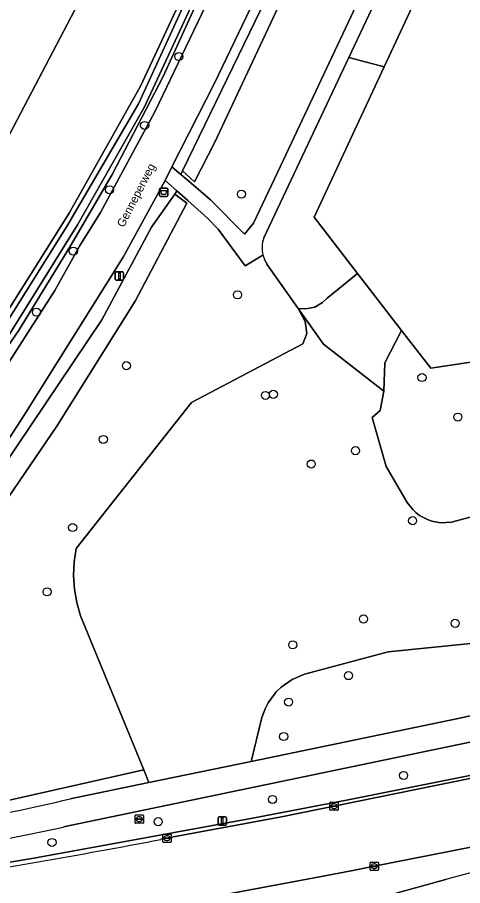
# Model space of a CAD drawing. Extents: x 160203 to 161530, y 379528 to 381797.
# Drawn here: x 160867 to 160920.7, y 380873.7 to 380978.3 of the extents above; entities that cross this region are included whole.
import ezdxf

# ---------------------------------------------------------------- set-up
doc = ezdxf.new("R2010")
doc.units = 0
for name, color, linetype in [('IMGEO_Afvalbak', 7, 'Continuous'), ('IMGEO_Berm_groen', 7, 'Continuous'), ('IMGEO_Boom', 7, 'Continuous'), ('IMGEO_Erf', 7, 'Continuous'), ('IMGEO_Fietspad_gesloten', 7, 'Continuous'), ('IMGEO_Grasland_agrarisch', 7, 'Continuous'), ('IMGEO_Groenvoorziening', 7, 'Continuous'), ('IMGEO_Kolk', 7, 'Continuous'), ('IMGEO_Lichtmast', 7, 'Continuous'), ('IMGEO_Loofbos', 7, 'Continuous'), ('IMGEO_Oever', 7, 'Continuous'), ('IMGEO_Openbare_ruimte_label', 7, 'Continuous'), ('IMGEO_Rijbaan_lokaal_gesloten', 7, 'Continuous'), ('IMGEO_Rijbaan_lokaal_open', 7, 'Continuous'), ('IMGEO_Rioolput', 7, 'Continuous'), ('IMGEO_Terreindeel_halfverhard', 7, 'Continuous'), ('IMGEO_Voetpad_halfverhard', 7, 'Continuous'), ('IMGEO_Voetpad_open', 7, 'Continuous'), ('IMGEO_Waterloop', 7, 'Continuous')]:
    doc.layers.add(name, color=color, linetype=linetype)

msp = doc.modelspace()

# ---------------------------------------------------------------- linework, layer by layer
at = {"layer": 'IMGEO_Afvalbak'}
for p, q in [((160884.18, 380956.88), (160884.18, 380957.67)), ((160884.18, 380957.67), (160884.18, 380956.88)), ((160884.28, 380957.77), (160885.07, 380957.77)), ((160885.07, 380957.77), (160884.28, 380957.77)), ((160885.17, 380957.67), (160885.17, 380956.88)), ((160885.17, 380956.88), (160885.17, 380957.67)), ((160885.07, 380956.78), (160884.28, 380956.78)), ((160884.28, 380956.78), (160885.07, 380956.78))]:
    msp.add_line(p, q, dxfattribs=at)
msp.add_lwpolyline([(160884.32, 380957.49), (160885.03, 380957.49), (160884.88, 380957.02), (160884.47, 380957.02), (160884.32, 380957.49)], dxfattribs=at)
for centre, start, end in [((160884.28, 380957.67), 90, 180), ((160884.28, 380957.67), 90, 180), ((160885.07, 380957.67), 0, 90), ((160885.07, 380957.67), 360, 90), ((160884.28, 380956.88), 180, 270), ((160884.28, 380956.88), 180, 270), ((160885.07, 380956.88), 270, 0), ((160885.07, 380956.88), 270, 0)]:
    msp.add_arc(centre, 0.1, start, end, dxfattribs=at)
at = {"layer": 'IMGEO_Berm_groen'}
msp.add_lwpolyline([(160903.11, 380993.15), (160903.75, 380994.27), (160903.74, 380994.85), (160902.43, 380994.82), (160901.43, 380992.62), (160890.8, 380970.43), (160885.68, 380960.32), (160886.73, 380959.43), (160886.96, 380959.86)], close=True, dxfattribs=at)
for points in [[(160934.56, 380893.86), (160921, 380890.93), (160872.61, 380880.82)], [(160998.03, 380891.65), (160999.49, 380891.83), (160989.42, 380892.42), (160952.06, 380884.24), (160949.3, 380883.67), (160949.22, 380884.02), (160939.29, 380881.99), (160930.13, 380880.09), (160925.35, 380879.1), (160916.8, 380877.42), (160910.05, 380876.08), (160907.28, 380875.55), (160901.96, 380874.53), (160894.01, 380873.03), (160886.98, 380871.73), (160886.33, 380871.62), (160884.79, 380871.34), (160882.6, 380870.58), (160869.67, 380866.12), (160869.92, 380864.47), (160867.84, 380864.13), (160868.11, 380862.53), (160872.74, 380863.26)], [(160850.52, 380876.66), (160860.78, 380875.68), (160869.03, 380877.04), (160882.43, 380879.51), (160895.18, 380881.82), (160906.72, 380884.04), (160922.19, 380887.13), (160938.38, 380890.52)], [(160893.97, 380867.8), (160903.4, 380870.29), (160918.79, 380874.53)]]:
    msp.add_lwpolyline(points, dxfattribs=at)
for centre, radius, start, end in [((160785.98, 381281.03), 409.49, 279.0693, 282.2148), ((161014.42, 380515.59), 371.47, 101.8451, 104.9191)]:
    msp.add_arc(centre, radius, start, end, dxfattribs=at)
at = {"layer": 'IMGEO_Boom'}
for centre in [(160886.5, 380973.62), (160882.39, 380965.32), (160878.15, 380957.57), (160894.05, 380957.04), (160873.79, 380950.18), (160893.57, 380944.92), (160869.35, 380942.83), (160880.19, 380936.39), (160915.81, 380934.95), (160896.94, 380932.8), (160897.9, 380932.93), (160920.12, 380930.19), (160877.41, 380927.5), (160907.79, 380926.14), (160902.46, 380924.53), (160873.71, 380916.88), (160914.67, 380917.71), (160870.63, 380909.14), (160908.76, 380905.87), (160919.81, 380905.35), (160900.23, 380902.76), (160906.94, 380899.05), (160899.73, 380895.86), (160899.14, 380891.71), (160913.58, 380887.02), (160897.79, 380884.13), (160884.02, 380881.46), (160871.22, 380878.95)]:
    msp.add_circle(centre, 0.489, dxfattribs=at)
at = {"layer": 'IMGEO_Erf'}
msp.add_lwpolyline([(160917.68, 380986.21), (160911.25, 380972.39), (160902.81, 380954.26), (160908.04, 380947.49), (160913.35, 380940.61), (160916.86, 380936.07), (160938.04, 380939.26), (160974.07, 380944.7), (160994.32, 380947.75), (160994.25, 380948.88), (160993.58, 380960.43), (160993.57, 380960.53), (160993.21, 380965.37), (160992.81, 380974.25), (160992.03, 380991.59)], dxfattribs=at)
at = {"layer": 'IMGEO_Fietspad_gesloten'}
for points in [[(160933.75, 380896.85), (160929.16, 380895.85), (160920.18, 380893.89), (160895.22, 380888.71), (160882.91, 380886.16), (160873.42, 380884.2)], [(160872.61, 380880.82), (160921, 380890.93), (160934.56, 380893.86)]]:
    msp.add_lwpolyline(points, dxfattribs=at)
for centre, radius, start, end in [((160802.53, 381188.95), 312.89, 277.602, 283.0955), ((160785.98, 381281.03), 409.49, 279.0693, 282.2148)]:
    msp.add_arc(centre, radius, start, end, dxfattribs=at)
at = {"layer": 'IMGEO_Grasland_agrarisch'}
msp.add_lwpolyline([(160858.7, 380950.21), (160907.85, 381043.87), (160906.45, 381043.75), (160903.91, 381043.31), (160892.97, 381036.64), (160860.97, 381016.14), (160810.15, 380983.79)], close=True, dxfattribs=at)
at = {"layer": 'IMGEO_Groenvoorziening'}
for points in [[(160911.25, 380972.39), (160906.98, 380973.52), (160896.73, 380951.77)], [(160897.11, 380948.63), (160900.89, 380943.28), (160901.8, 380943.21), (160902.88, 380943.43), (160903.83, 380943.98), (160904.36, 380944.51), (160908.04, 380947.49), (160902.81, 380954.26), (160911.25, 380972.39)], [(160858.53, 380914.13), (160877.24, 380941.9), (160883.2, 380953.05), (160886.02, 380957.03), (160886.26, 380957.43), (160884.85, 380958.68), (160879.8, 380949.47), (160867.87, 380930.41), (160854.51, 380909.81)], [(160928.17, 380919.9), (160919.37, 380917.55), (160918.04, 380917.47), (160916.97, 380917.66), (160916.46, 380917.84), (160915.51, 380918.35), (160915.08, 380918.68), (160914.69, 380919.05), (160914.03, 380919.9), (160911.49, 380924.25), (160909.79, 380930.15), (160910.76, 380931), (160911.19, 380933.32), (160903.93, 380938.99), (160900.89, 380943.28), (160901.72, 380941.71), (160901.91, 380940.25), (160901.44, 380939.01), (160888.04, 380931.93), (160874.15, 380914.36), (160873.91, 380912.74), (160873.83, 380911.1), (160873.93, 380909.47), (160874.2, 380907.85), (160874.64, 380906.26), (160882.28, 380887.7), (160882.91, 380886.16), (160895.22, 380888.71), (160895.25, 380888.88), (160896.51, 380894), (160896.9, 380895.06), (160897.28, 380895.78), (160898.25, 380897.08), (160898.83, 380897.64), (160900.15, 380898.58), (160901.64, 380899.21), (160902.42, 380899.41), (160911.74, 380901.91), (160921.7, 380902.93)], [(160873.42, 380884.2), (160882.91, 380886.16), (160882.28, 380887.7), (160860.9, 380882.9), (160843.89, 380880.32), (160843.51, 380879.66), (160841.06, 380879.63), (160842.68, 380883.89)]]:
    msp.add_lwpolyline(points, dxfattribs=at)
for points in [[(160913.35, 380940.61), (160908.04, 380947.49), (160904.36, 380944.51), (160903.83, 380943.98), (160902.88, 380943.43), (160901.8, 380943.21), (160900.89, 380943.28), (160903.93, 380938.99), (160911.19, 380933.32), (160911.31, 380936.72)], [(160929.8, 380899.21), (160929.31, 380899.91), (160928.12, 380901.13), (160927.45, 380901.64), (160925.94, 380902.43), (160924.31, 380902.9), (160923.46, 380903), (160921.7, 380902.93), (160911.74, 380901.91), (160902.42, 380899.41), (160901.64, 380899.21), (160900.15, 380898.58), (160898.83, 380897.64), (160898.25, 380897.08), (160897.28, 380895.78), (160896.9, 380895.06), (160896.51, 380894), (160895.25, 380888.88), (160895.22, 380888.71), (160920.18, 380893.89), (160929.16, 380895.85), (160929.18, 380895.93)]]:
    msp.add_lwpolyline(points, close=True, dxfattribs=at)
for centre, radius, start, end in [((160900.13, 380950.59), 3.6, 160.8327, 194.0431), ((160900.12, 380950.58), 3.58, 193.9543, 212.8524), ((160802.53, 381188.95), 312.89, 277.602, 283.0955)]:
    msp.add_arc(centre, radius, start, end, dxfattribs=at)
at = {"layer": 'IMGEO_Kolk'}
for p, q in [((160904.78, 380883.82), (160905.64, 380883.82)), ((160904.71, 380882.89), (160904.71, 380883.75)), ((160905.64, 380882.82), (160904.78, 380882.82)), ((160904.97, 380883.31), (160904.97, 380883.33)), ((160905.01, 380883.36), (160905.41, 380883.36)), ((160905.41, 380883.28), (160905.01, 380883.28)), ((160905.22, 380883.04), (160905.19, 380883.04)), ((160905.2, 380883.6), (160905.22, 380883.6)), ((160905.45, 380883.33), (160905.45, 380883.31)), ((160905.71, 380883.75), (160905.71, 380882.89)), ((160884.58, 380879.04), (160884.58, 380879.89)), ((160884.65, 380879.96), (160885.51, 380879.96)), ((160885.07, 380879.74), (160885.09, 380879.74)), ((160885.58, 380879.89), (160885.58, 380879.04)), ((160885.51, 380878.96), (160884.65, 380878.96)), ((160884.84, 380879.46), (160884.84, 380879.47)), ((160884.88, 380879.51), (160885.28, 380879.51)), ((160885.28, 380879.42), (160884.88, 380879.42)), ((160885.09, 380879.18), (160885.07, 380879.18)), ((160885.32, 380879.47), (160885.32, 380879.46)), ((160909.55, 380875.65), (160909.55, 380876.5)), ((160909.62, 380876.58), (160910.48, 380876.58)), ((160910.55, 380876.5), (160910.55, 380875.65)), ((160910.48, 380875.58), (160909.62, 380875.58)), ((160909.81, 380876.07), (160909.81, 380876.08)), ((160909.85, 380876.12), (160910.25, 380876.12)), ((160910.25, 380876.03), (160909.85, 380876.03)), ((160910.04, 380876.36), (160910.06, 380876.36)), ((160910.06, 380875.8), (160910.04, 380875.8)), ((160910.29, 380876.08), (160910.29, 380876.07))]:
    msp.add_line(p, q, dxfattribs=at)
for points in [[(160904.78, 380883.82), (160905.64, 380883.82)], [(160904.71, 380882.89), (160904.71, 380883.75)], [(160905.64, 380882.82), (160904.78, 380882.82)], [(160905.71, 380883.75), (160905.71, 380882.89)], [(160884.58, 380879.04), (160884.58, 380879.89)], [(160884.65, 380879.96), (160885.51, 380879.96)], [(160885.58, 380879.89), (160885.58, 380879.04)], [(160885.51, 380878.96), (160884.65, 380878.96)], [(160909.55, 380875.65), (160909.55, 380876.5)], [(160909.62, 380876.58), (160910.48, 380876.58)], [(160910.55, 380876.5), (160910.55, 380875.65)], [(160910.48, 380875.58), (160909.62, 380875.58)]]:
    msp.add_lwpolyline(points, dxfattribs=at)
for centre, radius, start, end in [((160904.79, 380883.74), 0.0765, 91.552, 178.448), ((160904.79, 380883.74), 0.0765, 91.552, 178.448), ((160905.63, 380883.74), 0.0765, 1.552, 88.448), ((160905.63, 380883.74), 0.0765, 1.552, 88.448), ((160904.79, 380882.89), 0.0765, 181.552, 268.448), ((160904.79, 380882.89), 0.0765, 181.552, 268.448), ((160905.01, 380883.32), 0.0403, 85.8775, 175.7526), ((160905, 380883.31), 0.0366, 178.938, 274.7102), ((160905.41, 380883.32), 0.0386, 1.7309, 96.639), ((160905.41, 380883.32), 0.043, 264.8664, 352.4533), ((160905.63, 380882.89), 0.0765, 271.552, 358.448), ((160905.63, 380882.89), 0.0765, 271.552, 358.448), ((160884.66, 380879.89), 0.0765, 91.552, 178.448), ((160884.66, 380879.89), 0.0765, 91.552, 178.448), ((160885.5, 380879.89), 0.0765, 1.552, 88.448), ((160885.5, 380879.89), 0.0765, 1.552, 88.448), ((160884.66, 380879.04), 0.0765, 181.552, 268.448), ((160884.66, 380879.04), 0.0765, 181.552, 268.448), ((160884.88, 380879.47), 0.0403, 85.8775, 175.7526), ((160884.88, 380879.46), 0.0366, 178.938, 274.7102), ((160885.28, 380879.47), 0.0386, 1.7309, 96.639), ((160885.28, 380879.46), 0.043, 264.8664, 352.4533), ((160885.5, 380879.04), 0.0765, 271.552, 358.448), ((160885.5, 380879.04), 0.0765, 271.552, 358.448), ((160909.63, 380876.5), 0.0765, 91.552, 178.448), ((160909.63, 380876.5), 0.0765, 91.552, 178.448), ((160910.47, 380876.5), 0.0765, 1.552, 88.448), ((160910.47, 380876.5), 0.0765, 1.552, 88.448), ((160909.63, 380875.65), 0.0765, 181.552, 268.448), ((160909.63, 380875.65), 0.0765, 181.552, 268.448), ((160909.85, 380876.08), 0.0403, 85.8775, 175.7526), ((160909.85, 380876.07), 0.0366, 178.938, 274.7102), ((160910.25, 380876.08), 0.0386, 1.7309, 96.639), ((160910.25, 380876.08), 0.043, 264.8664, 352.4533), ((160910.47, 380875.65), 0.0765, 271.552, 358.448), ((160910.47, 380875.65), 0.0765, 271.552, 358.448)]:
    msp.add_arc(centre, radius, start, end, dxfattribs=at)
for centre, major_axis, ratio, start_param, end_param in [((160905.2, 380883.32), (-0.387, 0.002), 0.722429, 4.712389, 7.853982), ((160905.22, 380883.32), (-0.39, 0.002), 0.717154, 1.570796, 4.712389), ((160885.07, 380879.46), (-0.387, 0.002), 0.722429, 4.712389, 7.853982), ((160885.09, 380879.46), (-0.39, 0.002), 0.717154, 1.570796, 4.712389), ((160910.04, 380876.08), (-0.387, 0.002), 0.722429, 4.712389, 7.853982), ((160910.06, 380876.08), (-0.39, 0.002), 0.717154, 1.570796, 4.712389)]:
    msp.add_ellipse(centre, major_axis=major_axis, ratio=ratio, start_param=start_param, end_param=end_param, dxfattribs=at)
at = {"layer": 'IMGEO_Lichtmast'}
for p, q in [((160878.95, 380947.68), (160879.74, 380947.68)), ((160879.74, 380947.68), (160878.95, 380947.68)), ((160878.85, 380946.78), (160878.85, 380947.58)), ((160878.85, 380947.58), (160878.85, 380946.78)), ((160879.74, 380946.68), (160878.95, 380946.68)), ((160878.95, 380946.68), (160879.74, 380946.68)), ((160879.84, 380947.58), (160879.84, 380946.78)), ((160879.84, 380946.78), (160879.84, 380947.58)), ((160891.24, 380881.14), (160891.24, 380881.93)), ((160891.24, 380881.93), (160891.24, 380881.14)), ((160891.34, 380882.03), (160892.13, 380882.03)), ((160892.13, 380882.03), (160891.34, 380882.03)), ((160892.23, 380881.93), (160892.23, 380881.14)), ((160892.23, 380881.14), (160892.23, 380881.93)), ((160892.13, 380881.04), (160891.34, 380881.04)), ((160891.34, 380881.04), (160892.13, 380881.04))]:
    msp.add_line(p, q, dxfattribs=at)
for points in [[(160879.27, 380947.56), (160879.42, 380947.56), (160879.42, 380946.81), (160879.27, 380946.81), (160879.27, 380947.56)], [(160891.66, 380881.91), (160891.81, 380881.91), (160891.81, 380881.16), (160891.66, 380881.16), (160891.66, 380881.91)]]:
    msp.add_lwpolyline(points, dxfattribs=at)
for centre, start, end in [((160878.95, 380947.58), 90, 180), ((160878.95, 380947.58), 90, 180), ((160879.74, 380947.58), 0, 90), ((160879.74, 380947.58), 360, 90), ((160878.95, 380946.78), 180, 270), ((160878.95, 380946.78), 180, 270), ((160879.74, 380946.78), 270, 0), ((160879.74, 380946.78), 270, 0), ((160891.34, 380881.93), 90, 180), ((160891.34, 380881.93), 90, 180), ((160892.13, 380881.93), 0, 90), ((160892.13, 380881.93), 360, 90), ((160891.34, 380881.14), 180, 270), ((160891.34, 380881.14), 180, 270), ((160892.13, 380881.14), 270, 0), ((160892.13, 380881.14), 270, 0)]:
    msp.add_arc(centre, 0.1, start, end, dxfattribs=at)
at = {"layer": 'IMGEO_Loofbos'}
for points in [[(160907.85, 381043.87), (160858.7, 380950.21), (160856.23, 380945.5), (160853.62, 380940.52), (160826.35, 380889.51), (160801.79, 380885.77), (160750.8, 380882.93), (160734.94, 380882.84), (160723.88, 380883.66), (160707.62, 380884.39), (160666.07, 380892.23), (160666.2, 380893.06), (160666.97, 380895.2), (160673.83, 380902.02), (160675.9, 380904.09), (160673.25, 380902.33), (160665.49, 380896.7), (160663.76, 380895.08), (160661.52, 380893.09)], [(160849.16, 380917.09), (160865.84, 380942.85), (160873.3, 380954.74), (160881.89, 380970.06), (160895.87, 381000), (160897.9, 381004.22), (160914.24, 381044.58), (160915.48, 381044.08), (160911.82, 381034.66), (160897.77, 381000), (160884.61, 380971.23), (160878.46, 380959.43), (160873.47, 380950.83), (160867.18, 380940.56), (160863.19, 380934.81), (160848.01, 380912.03)], [(160910.83, 380990.55), (160905.74, 380994.06), (160905.31, 380994.23), (160903.74, 380994.85), (160903.75, 380994.27), (160905.04, 380993.65), (160904.54, 380992.54), (160890.84, 380963.29), (160888.41, 380958.52), (160886.96, 380959.86), (160886.73, 380959.43), (160888.26, 380958.11), (160890.32, 380956.35), (160894.41, 380952.23), (160895.52, 380953.54), (160898.75, 380960.41), (160911.47, 380987.47)], [(160854.02, 380918.09), (160871.57, 380945.42), (160874.53, 380950.78), (160877.07, 380954.85), (160883.67, 380967.04), (160892.95, 380986.45)], [(160896.64, 380949.71), (160894.49, 380948.42), (160891.24, 380952.81), (160889.99, 380954.13), (160887.58, 380956.27), (160886.26, 380957.43), (160886.02, 380957.03), (160887.46, 380955.94), (160881.24, 380944.17), (160871.8, 380929.08), (160863.36, 380916.75)], [(160874.15, 380914.36), (160888.04, 380931.93), (160901.44, 380939.01), (160901.91, 380940.25), (160901.72, 380941.71), (160900.89, 380943.28), (160897.11, 380948.63)], [(160938.04, 380939.26), (160916.86, 380936.07), (160913.35, 380940.61), (160911.31, 380936.72), (160911.19, 380933.32), (160910.76, 380931), (160909.79, 380930.15), (160911.49, 380924.25), (160914.03, 380919.9), (160914.69, 380919.05), (160915.08, 380918.68), (160915.51, 380918.35), (160916.46, 380917.84), (160916.97, 380917.66), (160918.04, 380917.47), (160919.37, 380917.55), (160928.17, 380919.9)], [(160860.9, 380882.9), (160882.28, 380887.7), (160874.64, 380906.26), (160874.2, 380907.85), (160873.93, 380909.47), (160873.83, 380911.1), (160873.91, 380912.74), (160874.15, 380914.36)]]:
    msp.add_lwpolyline(points, dxfattribs=at)
msp.add_arc((160900.12, 380950.58), 3.58, 193.9543, 212.8524, dxfattribs=at)
at = {"layer": 'IMGEO_Oever'}
for points in [[(160848.01, 380912.03), (160863.19, 380934.81), (160867.18, 380940.56), (160873.47, 380950.83), (160878.46, 380959.43), (160884.61, 380971.23), (160897.77, 381000), (160911.82, 381034.66), (160915.48, 381044.08), (160914.24, 381044.58), (160897.9, 381004.22), (160895.87, 381000), (160881.89, 380970.06), (160873.3, 380954.74), (160865.84, 380942.85), (160849.16, 380917.09)], [(160807.28, 380879.85), (160818.14, 380880.8), (160831.95, 380881.97), (160833.09, 380882.65), (160835.01, 380887.77), (160838.48, 380896.48), (160843.29, 380905.49), (160848.69, 380915.44), (160863.25, 380937.65), (160873.05, 380953.22), (160881.66, 380967.92), (160892.36, 380991.35)], [(160891.91, 380988.16), (160882.32, 380967.5), (160874.3, 380953.34), (160861.97, 380933.61), (160847.84, 380912.49), (160847, 380911.39), (160846.33, 380910.2), (160845.54, 380908.33), (160839.58, 380896.57), (160835.33, 380887.21), (160833.62, 380881.94), (160832.35, 380880.66), (160825.55, 380880.04), (160807.31, 380878.5)]]:
    msp.add_lwpolyline(points, dxfattribs=at)
at = {"layer": 'IMGEO_Rijbaan_lokaal_gesloten'}
for points in [[(160885.68, 380960.32), (160890.8, 380970.43), (160901.43, 380992.62)], [(160892.95, 380986.45), (160883.67, 380967.04), (160877.07, 380954.85), (160874.53, 380950.78), (160871.57, 380945.42), (160854.02, 380918.09)], [(160854.51, 380909.81), (160867.87, 380930.41), (160879.8, 380949.47), (160884.85, 380958.68), (160885.68, 380960.32)], [(160947.24, 380891.88), (160898.87, 380882.02), (160884.34, 380879.33)], [(160839.83, 380865.64), (160834.99, 380865), (160833.58, 380860.78), (160840.24, 380861.63), (160843.14, 380862.05), (160847.14, 380863.48), (160856, 380866.69), (160882.5, 380871.05), (160882.6, 380870.58), (160884.79, 380871.34), (160886.33, 380871.62), (160886.98, 380871.73), (160894.01, 380873.03), (160901.96, 380874.53), (160907.28, 380875.55), (160910.05, 380876.08), (160916.8, 380877.42), (160925.35, 380879.1)]]:
    msp.add_lwpolyline(points, dxfattribs=at)
msp.add_arc((160742.1, 381615.99), 750.28, 278.63489, 280.92837, dxfattribs=at)
at = {"layer": 'IMGEO_Rijbaan_lokaal_open'}
for points in [[(160884.34, 380879.33), (160898.87, 380882.02), (160947.24, 380891.88)], [(160922.19, 380887.13), (160906.72, 380884.04), (160895.18, 380881.82), (160882.43, 380879.51), (160869.03, 380877.04), (160860.78, 380875.68), (160858.65, 380875.32), (160853.24, 380874.49), (160853.31, 380874), (160854.74, 380874.22)], [(160918.79, 380874.53), (160903.4, 380870.29), (160893.97, 380867.8)]]:
    msp.add_lwpolyline(points, dxfattribs=at)
for centre, radius, start, end in [((160742.1, 381615.99), 750.28, 278.63489, 280.92837), ((161014.42, 380515.59), 371.47, 101.8451, 104.9191), ((161019.42, 380494.92), 389.71, 101.948, 104.7709)]:
    msp.add_arc(centre, radius, start, end, dxfattribs=at)
at = {"layer": 'IMGEO_Rioolput'}
for p, q in [((160881.23, 380881.33), (160881.23, 380882.19)), ((160881.31, 380882.26), (160882.16, 380882.26)), ((160881.49, 380881.75), (160881.49, 380881.77)), ((160881.54, 380881.8), (160881.93, 380881.8)), ((160881.72, 380882.04), (160881.75, 380882.04)), ((160881.98, 380881.77), (160881.98, 380881.75)), ((160882.23, 380882.19), (160882.23, 380881.33)), ((160882.16, 380881.26), (160881.31, 380881.26)), ((160881.93, 380881.72), (160881.53, 380881.72)), ((160881.74, 380881.48), (160881.72, 380881.48))]:
    msp.add_line(p, q, dxfattribs=at)
for points in [[(160881.23, 380881.33), (160881.23, 380882.19)], [(160881.31, 380882.26), (160882.16, 380882.26)], [(160882.23, 380882.19), (160882.23, 380881.33)], [(160882.16, 380881.26), (160881.31, 380881.26)]]:
    msp.add_lwpolyline(points, dxfattribs=at)
for centre, radius, start, end in [((160881.31, 380882.18), 0.0765, 91.552, 178.448), ((160881.31, 380882.18), 0.0765, 91.552, 178.448), ((160881.53, 380881.76), 0.0403, 85.8775, 175.7526), ((160881.53, 380881.75), 0.0366, 178.938, 274.7102), ((160881.94, 380881.76), 0.0386, 1.7309, 96.639), ((160881.93, 380881.76), 0.043, 264.8664, 352.4533), ((160882.16, 380882.18), 0.0765, 1.552, 88.448), ((160882.16, 380882.18), 0.0765, 1.552, 88.448), ((160881.31, 380881.33), 0.0765, 181.552, 268.448), ((160881.31, 380881.33), 0.0765, 181.552, 268.448), ((160882.16, 380881.33), 0.0765, 271.552, 358.448), ((160882.16, 380881.33), 0.0765, 271.552, 358.448)]:
    msp.add_arc(centre, radius, start, end, dxfattribs=at)
for centre, major_axis, ratio, start_param, end_param in [((160881.72, 380881.76), (-0.387, 0.002), 0.722429, 4.712389, 7.853982), ((160881.74, 380881.76), (-0.39, 0.002), 0.717154, 1.570796, 4.712389)]:
    msp.add_ellipse(centre, major_axis=major_axis, ratio=ratio, start_param=start_param, end_param=end_param, dxfattribs=at)
at = {"layer": 'IMGEO_Terreindeel_halfverhard'}
msp.add_lwpolyline([(160917.68, 380986.21), (160913.8, 380988), (160906.98, 380973.52), (160911.25, 380972.39)], close=True, dxfattribs=at)
at = {"layer": 'IMGEO_Voetpad_halfverhard'}
for points in [[(160896.73, 380951.77), (160906.98, 380973.52), (160913.8, 380988), (160917.68, 380986.21), (160918.58, 380988.13), (160920.18, 380991.56), (160918.57, 380992.96), (160917.12, 380994.86), (160917.39, 380995.43), (160917.64, 380996.15), (160919.39, 381000)], [(160911.78, 380988.14), (160911.47, 380987.47), (160898.75, 380960.41), (160895.52, 380953.54), (160894.41, 380952.23), (160890.32, 380956.35), (160888.26, 380958.11), (160886.73, 380959.43), (160885.68, 380960.32), (160884.85, 380958.68), (160886.26, 380957.43), (160887.58, 380956.27), (160889.99, 380954.13), (160891.24, 380952.81), (160894.49, 380948.42), (160896.64, 380949.71)]]:
    msp.add_lwpolyline(points, dxfattribs=at)
msp.add_arc((160900.13, 380950.59), 3.6, 160.8327, 194.0431, dxfattribs=at)
at = {"layer": 'IMGEO_Voetpad_open'}
msp.add_arc((161019.42, 380494.92), 389.71, 101.948, 104.7709, dxfattribs=at)
at = {"layer": 'IMGEO_Waterloop'}
msp.add_lwpolyline([(160886.96, 380959.86), (160888.41, 380958.52), (160890.84, 380963.29), (160904.54, 380992.54), (160905.04, 380993.65), (160903.75, 380994.27), (160903.11, 380993.15)], close=True, dxfattribs=at)
for points in [[(160892.36, 380991.35), (160881.66, 380967.92), (160873.05, 380953.22), (160863.25, 380937.65), (160848.69, 380915.44), (160843.29, 380905.49), (160838.48, 380896.48), (160835.01, 380887.77), (160833.09, 380882.65), (160831.95, 380881.97), (160818.14, 380880.8), (160807.28, 380879.85)], [(160807.31, 380878.5), (160825.55, 380880.04), (160832.35, 380880.66), (160833.62, 380881.94), (160835.33, 380887.21), (160839.58, 380896.57), (160845.54, 380908.33), (160846.33, 380910.2), (160847, 380911.39), (160847.84, 380912.49), (160861.97, 380933.61), (160874.3, 380953.34), (160882.32, 380967.5), (160891.91, 380988.16)], [(160871.8, 380929.08), (160881.24, 380944.17), (160887.46, 380955.94), (160886.02, 380957.03), (160883.2, 380953.05), (160877.24, 380941.9), (160858.53, 380914.13), (160851.42, 380901.38), (160849.55, 380898.33), (160846.07, 380891.47)], [(160842.68, 380883.89), (160841.06, 380879.63), (160843.51, 380879.66), (160843.89, 380880.32), (160843.89, 380880.32), (160846.39, 380886.54), (160848.55, 380890.86), (160852.84, 380898.88), (160859.18, 380910.24), (160863.36, 380916.75), (160871.8, 380929.08)]]:
    msp.add_lwpolyline(points, dxfattribs=at)

# ---------------------------------------------------------------- texts
at = {"layer": 'IMGEO_Openbare_ruimte_label'}
msp.add_text('Genneperweg', height=1, rotation=62.6922, dxfattribs=at).set_placement((160879.87, 380952.96))

doc.saveas('drawing.dxf')
